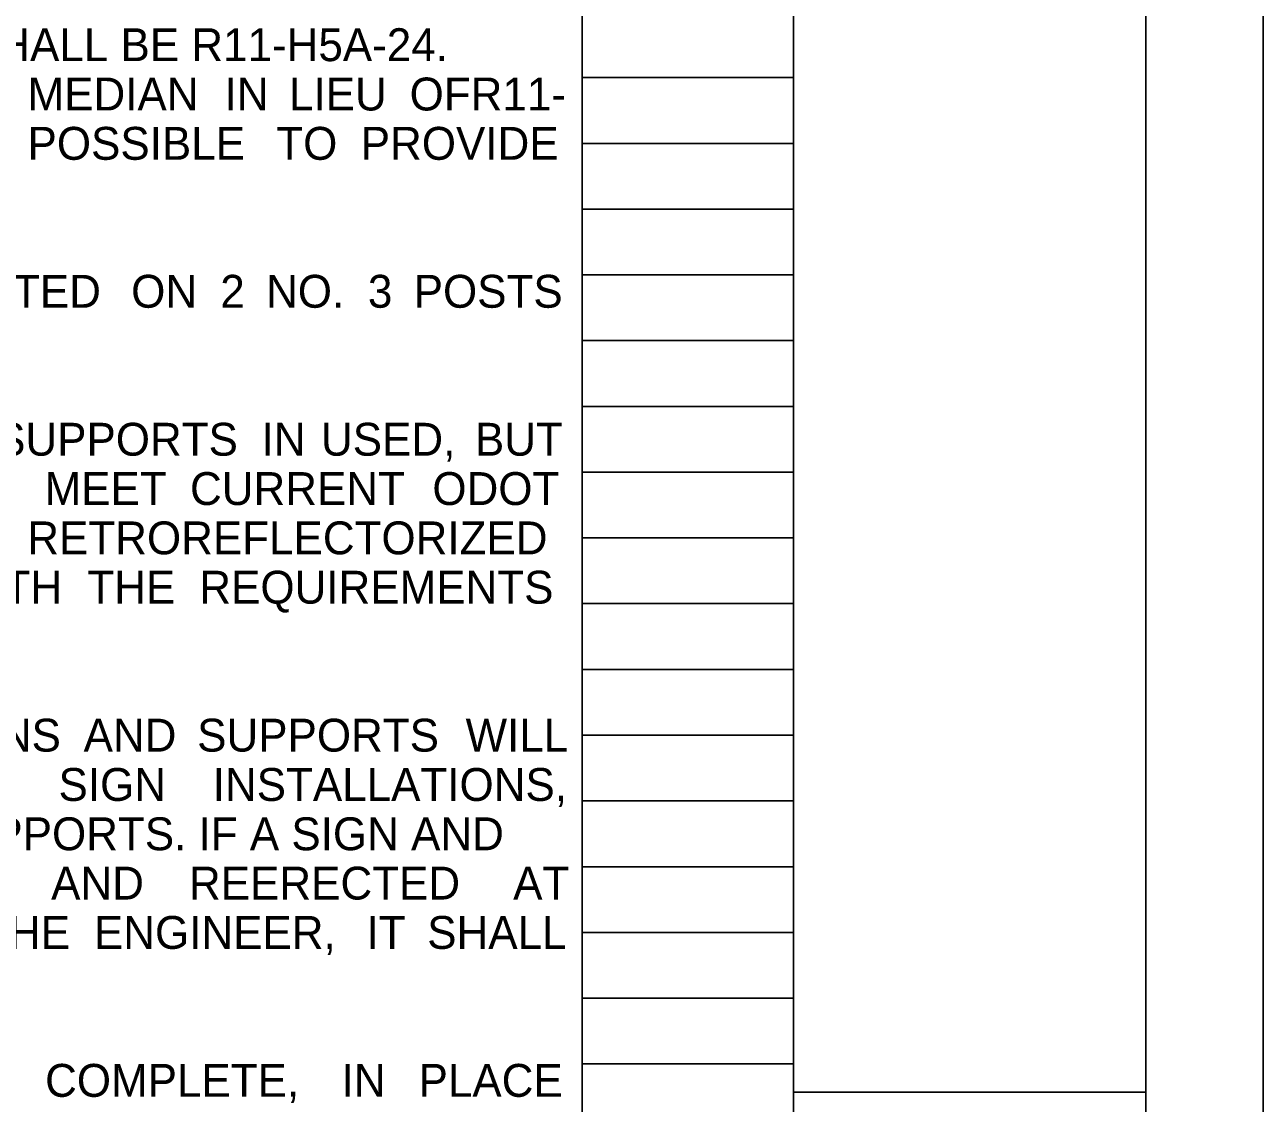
# Model space of a CAD drawing. Extents: x 0 to 43.6, y -18 to 22.
# Drawn here: x 28.73 to 34, y 4.45 to 9.04 of the extents above; entities that cross this region are included whole.
import ezdxf

# ---------------------------------------------------------------- set-up
doc = ezdxf.new("R2010")
doc.units = 0
for name, color, linetype in [('SH_Border', 7, 'Continuous'), ('SH_Cut_Line', 7, 'Continuous'), ('SH_Data', 7, 'Continuous'), ('SH_Text', 7, 'Continuous')]:
    doc.layers.add(name, color=color, linetype=linetype)

msp = doc.modelspace()

# ---------------------------------------------------------------- linework, layer by layer
at = {"layer": 'SH_Border'}
for p, q in [((32, 0.5), (32, 21.5)), ((32, 4.5), (33.5, 4.5))]:
    msp.add_line(p, q, dxfattribs=at)
msp.add_lwpolyline([(1.5, 21.5), (33.5, 21.5), (33.5, 0.5), (1.5, 0.5)], close=True, dxfattribs=at)
at = {"layer": 'SH_Cut_Line'}
msp.add_lwpolyline([(0, 0), (34, 0), (34, 22), (0, 22)], close=True, dxfattribs=at)
at = {"layer": 'SH_Data'}
for p, q in [((31.1, 0.98), (31.1, 21.14)), ((32, 0.98), (32, 21.14)), ((31.1, 8.82), (32, 8.82)), ((31.1, 8.54), (32, 8.54)), ((31.1, 8.26), (32, 8.26)), ((31.1, 7.98), (32, 7.98)), ((31.1, 7.7), (32, 7.7)), ((31.1, 7.42), (32, 7.42)), ((31.1, 7.14), (32, 7.14)), ((31.1, 6.86), (32, 6.86)), ((31.1, 6.58), (32, 6.58)), ((31.1, 6.3), (32, 6.3)), ((31.1, 6.02), (32, 6.02)), ((31.1, 5.74), (32, 5.74)), ((31.1, 5.46), (32, 5.46)), ((31.1, 5.18), (32, 5.18)), ((31.1, 4.9), (32, 4.9)), ((31.1, 4.62), (32, 4.62))]:
    msp.add_line(p, q, dxfattribs=at)

# ---------------------------------------------------------------- texts
at = {"layer": 'SH_Text'}
for s, p in [('R11-H5A-48. SIGNS USED ON THE RAMPS SHALL BE R11-H5A-24.', (24.66, 8.89)), ('MEDIAN ', (28.7376, 8.68)), ('IN ', (29.5771, 8.68)), ('LIEU ', (29.8513, 8.68)), ('OFR11-', (30.3648, 8.68)), ('POSSIBLE ', (28.7376, 8.47)), ('TO ', (29.797, 8.47)), ('PROVIDE', (30.1567, 8.47)), ('MOUNTED ', (28.1039, 7.84)), ('ON ', (29.179, 7.84)), ('2 ', (29.5585, 7.84)), ('NO. ', (29.7534, 7.84)), ('3 ', (30.1872, 7.84)), ('POSTS', (30.3821, 7.84)), ('SUPPORTS ', (28.6037, 7.21)), ('IN ', (29.7341, 7.21)), ('USED, ', (29.9873, 7.21)), ('BUT', (30.6428, 7.21)), ('MEET ', (28.8103, 7)), ('CURRENT ', (29.4295, 7)), ('ODOT', (30.4617, 7)), ('RETROREFLECTORIZED', (28.7366, 6.79)), ('WITH ', (28.407, 6.58)), ('THE ', (28.9923, 6.58)), ('REQUIREMENTS', (29.4692, 6.58)), ('SIGNS ', (28.2972, 5.95)), ('AND ', (28.9764, 5.95)), ('SUPPORTS ', (29.46, 5.95)), ('WILL', (30.6032, 5.95)), ('SIGN ', (28.8696, 5.74)), ('INSTALLATIONS,', (29.5264, 5.74)), ('INCLUDING THE SIGN AND NECESSARY SUPPORTS. IF A SIGN AND', (24.66, 5.53)), ('AND ', (28.8381, 5.32)), ('REERECTED ', (29.4252, 5.32)), ('AT', (30.8058, 5.32)), ('THE ', (28.5443, 5.11)), ('ENGINEER, ', (29.0203, 5.11)), ('IT ', (30.1812, 5.11)), ('SHALL', (30.4398, 5.11)), ('COMPLETE, ', (28.8124, 4.48)), ('IN ', (30.0751, 4.48)), ('PLACE ', (30.403, 4.48))]:
    msp.add_text(s, height=0.14, dxfattribs=at).set_placement(p)

doc.saveas('drawing.dxf')
